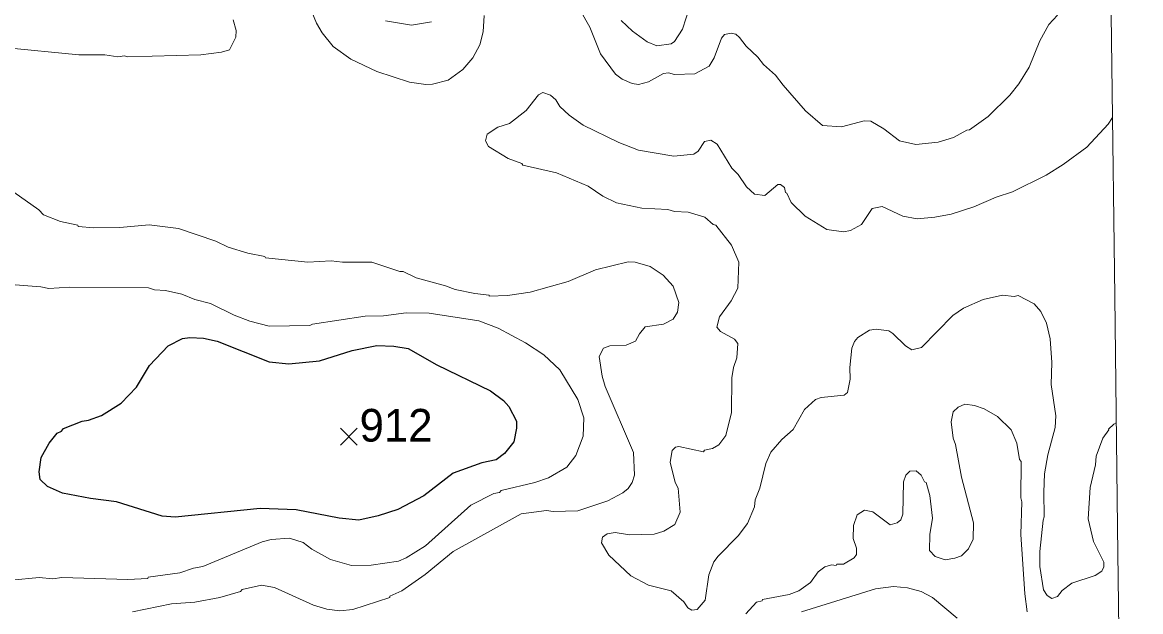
# Model space of a CAD drawing. Extents: x 265.7 to 292.1, y 7676.2 to 7704.2.
# Drawn here: x 289.24 to 291.975, y 7691.003 to 7692.446 of the extents above; entities that cross this region are included whole.
import ezdxf
from ezdxf.enums import TextEntityAlignment as Align

# ---------------------------------------------------------------- set-up
doc = ezdxf.new("R2010")
doc.units = 0
doc.header["$LTSCALE"] = 0.032
for name, color, linetype, lineweight in [('1', 7, 'Continuous', 25), ('2', 7, 'Continuous', 13), ('21', 7, 'Continuous', 25), ('63', 7, 'Continuous', 25)]:
    doc.layers.add(name, color=color, linetype=linetype, lineweight=lineweight)
doc.layers.add('61', color=7, linetype='Continuous')

msp = doc.modelspace()

# ---------------------------------------------------------------- linework, layer by layer
at = {"layer": '1'}
msp.add_lwpolyline([(289.9665, 7691.6176), (290.0463, 7691.6424), (290.107, 7691.6551), (290.1485, 7691.6535), (290.1836, 7691.648), (290.2538, 7691.6073), (290.3847, 7691.5442), (290.4166, 7691.5203), (290.4293, 7691.5059), (290.4485, 7691.47), (290.4485, 7691.4525), (290.4421, 7691.419), (290.419, 7691.3902), (290.399, 7691.375), (290.3639, 7691.3679), (290.2937, 7691.3423), (290.2219, 7691.2873), (290.158, 7691.2538), (290.1102, 7691.2378), (290.0623, 7691.2274), (290.0144, 7691.2322), (289.9091, 7691.253), (289.8213, 7691.2561), (289.6138, 7691.2346), (289.5819, 7691.237), (289.4702, 7691.2721), (289.4064, 7691.2801), (289.3377, 7691.2937), (289.301, 7691.3096), (289.2835, 7691.3272), (289.2803, 7691.3455), (289.2859, 7691.3806), (289.305, 7691.4158), (289.325, 7691.4405), (289.3353, 7691.4453), (289.3401, 7691.4517), (289.3856, 7691.47), (289.4016, 7691.4724), (289.4335, 7691.4836), (289.4814, 7691.5139), (289.5189, 7691.553), (289.5508, 7691.6057), (289.5963, 7691.6543), (289.6314, 7691.6719), (289.6489, 7691.6743), (289.6825, 7691.6727), (289.716, 7691.6655), (289.8436, 7691.6152), (289.8915, 7691.6104)], close=True, dxfattribs=at)
at = {"layer": '2'}
for points in [[(289.9362, 7692.4994), (289.9593, 7692.4435), (289.9729, 7692.4204), (290, 7692.3869), (290.0431, 7692.3557), (290.107, 7692.3254), (290.1868, 7692.2991), (290.2267, 7692.2935), (290.2426, 7692.2943), (290.2809, 7692.3047), (290.3168, 7692.3302), (290.3416, 7692.3589), (290.3583, 7692.3909), (290.3671, 7692.4228), (290.3695, 7692.4627)], [(290.8722, 7692.485), (290.8547, 7692.4292), (290.8347, 7692.3988), (290.8267, 7692.3933), (290.7916, 7692.3885), (290.7677, 7692.398), (290.7318, 7692.4244), (290.7046, 7692.4507)], [(290.6041, 7692.4755), (290.628, 7692.434), (290.6536, 7692.3685), (290.6903, 7692.3191), (290.707, 7692.3071), (290.731, 7692.2959), (290.7469, 7692.2935), (290.7709, 7692.3007), (290.8076, 7692.3206), (290.8204, 7692.3222), (290.8347, 7692.3182), (290.885, 7692.3198), (290.9201, 7692.339), (290.9321, 7692.3589), (290.9496, 7692.4068), (290.9576, 7692.4164), (290.9736, 7692.4196), (290.9847, 7692.4172), (290.9943, 7692.4092), (291.0103, 7692.3877), (291.039, 7692.3605), (291.0525, 7692.343), (291.0821, 7692.3167), (291.1004, 7692.2919), (291.1555, 7692.2297), (291.197, 7692.1938), (291.2433, 7692.1898), (291.2991, 7692.2049), (291.3151, 7692.2041), (291.347, 7692.185), (291.3853, 7692.1563), (291.4252, 7692.1467), (291.4795, 7692.1523), (291.5178, 7692.1642), (291.5497, 7692.1818), (291.5569, 7692.1826), (291.6024, 7692.2153), (291.655, 7692.268), (291.6774, 7692.2951), (291.7029, 7692.3366), (291.7284, 7692.4004), (291.7508, 7692.4403), (291.7715, 7692.4635)], [(288.8063, 7692.4491), (288.8781, 7692.4379), (288.8941, 7692.4379), (288.9659, 7692.4236), (288.9818, 7692.4236), (289.0074, 7692.4164), (289.1766, 7692.3901), (289.1941, 7692.3845), (289.3776, 7692.3661), (289.4415, 7692.3661), (289.4734, 7692.3613), (289.4894, 7692.3637), (289.4973, 7692.3613), (289.6761, 7692.3661), (289.7271, 7692.3733), (289.7463, 7692.3789), (289.7615, 7692.41), (289.763, 7692.426), (289.7551, 7692.4523)], [(290.2402, 7692.4475), (290.1916, 7692.4387), (290.1277, 7692.4499)], [(290.9751, 7691.5754), (290.9791, 7691.6009), (290.9871, 7691.6248), (290.9895, 7691.6599), (290.9815, 7691.6703), (290.9472, 7691.6895), (290.9384, 7691.6998), (290.9448, 7691.7254), (290.9736, 7691.7645), (290.9895, 7691.7956), (290.9919, 7691.8586), (290.9744, 7691.9009), (290.936, 7691.9496), (290.9297, 7691.9512), (290.9089, 7691.9687), (290.8682, 7691.9815), (290.8347, 7691.9831), (290.8188, 7691.9879), (290.7549, 7691.9911), (290.6927, 7692.0038), (290.6592, 7692.0206), (290.6241, 7692.0453), (290.5459, 7692.0773), (290.4637, 7692.0964), (290.4613, 7692.1004), (290.4278, 7692.1124), (290.3799, 7692.1419), (290.3727, 7692.1563), (290.3767, 7692.1722), (290.403, 7692.189), (290.4309, 7692.1986), (290.4724, 7692.2305), (290.502, 7692.2688), (290.5131, 7692.2744), (290.5315, 7692.268), (290.545, 7692.256), (290.5546, 7692.2401), (290.577, 7692.2185), (290.6113, 7692.1946), (290.6991, 7692.1515), (290.7469, 7692.1331), (290.8331, 7692.118), (290.8826, 7692.1235), (290.893, 7692.1307), (290.9081, 7692.1539), (290.9241, 7692.1579), (290.9392, 7692.1475), (290.9751, 7692.0892), (290.9903, 7692.0733), (291.0111, 7692.043), (291.0302, 7692.0254), (291.0557, 7692.0222), (291.0877, 7692.0493), (291.0941, 7692.0493), (291.1036, 7692.0414), (291.1068, 7692.0294), (291.11, 7692.0278), (291.1204, 7692.0047), (291.1547, 7691.9711), (291.2074, 7691.9392), (291.2481, 7691.9328), (291.2656, 7691.9368), (291.2927, 7691.9512), (291.3183, 7691.9903), (291.343, 7691.9951), (291.3933, 7691.9711), (291.4284, 7691.9647), (291.4715, 7691.9687), (291.5114, 7691.9767), (291.5672, 7691.9943), (291.6215, 7692.0182), (291.6614, 7692.031), (291.7444, 7692.0717), (291.7859, 7692.098), (291.8433, 7692.1403), (291.896, 7692.197), (291.9065, 7692.2129)], [(289.55, 7691.9504), (289.4782, 7691.944), (289.4143, 7691.9432), (289.376, 7691.9464), (289.3752, 7691.9496), (289.333, 7691.9584), (289.2915, 7691.9751), (289.2795, 7691.9871), (289.1095, 7692.1068)], [(289.8341, 7691.8698), (289.8325, 7691.873), (289.791, 7691.881), (289.7431, 7691.8953), (289.7128, 7691.9105), (289.6218, 7691.9416), (289.55, 7691.9504)], [(289.5093, 7691.0032), (289.6043, 7691.0224), (289.6617, 7691.0271), (289.7224, 7691.0383), (289.7734, 7691.0527), (289.7774, 7691.0575), (289.8245, 7691.0686), (289.8564, 7691.0623), (289.9522, 7691.0192), (289.9841, 7691.0096), (290.016, 7691.0056), (290.0479, 7691.0088), (290.1389, 7691.0383), (290.1389, 7691.0415), (290.1676, 7691.0543), (290.2251, 7691.0942), (290.2937, 7691.1508), (290.4597, 7691.2426), (290.5219, 7691.2514), (290.5379, 7691.249), (290.5985, 7691.2506), (290.6719, 7691.2745), (290.7086, 7691.2945), (290.7214, 7691.3048), (290.731, 7691.3192), (290.7374, 7691.3376), (290.735, 7691.3934), (290.6655, 7691.5546), (290.6576, 7691.5801), (290.6504, 7691.628), (290.6616, 7691.6488), (290.6767, 7691.6543), (290.7166, 7691.6559), (290.7398, 7691.6655), (290.7493, 7691.6839), (290.7629, 7691.7006), (290.8076, 7691.707), (290.8315, 7691.7198), (290.8419, 7691.7365), (290.8459, 7691.7605), (290.8315, 7691.8004), (290.8068, 7691.8275), (290.7757, 7691.8482), (290.739, 7691.8586), (290.7214, 7691.8594), (290.6416, 7691.8403), (290.5746, 7691.8115), (290.482, 7691.7852), (290.4262, 7691.7772), (290.3815, 7691.7756), (290.3815, 7691.778), (290.3464, 7691.782), (290.2985, 7691.7924), (290.2745, 7691.8012), (290.2027, 7691.8203), (290.1708, 7691.8363), (290.1628, 7691.8363), (290.0942, 7691.8586), (290.0224, 7691.8586), (289.9953, 7691.8618), (289.9378, 7691.8586), (289.8341, 7691.8698)], [(289.2117, 7691.8044), (289.2851, 7691.7988), (289.3042, 7691.7948), (289.3553, 7691.798), (289.5484, 7691.7964), (289.5628, 7691.7916), (289.5899, 7691.7892), (289.6298, 7691.7804), (289.6617, 7691.7677), (289.7, 7691.7581), (289.7575, 7691.7294), (289.7958, 7691.7142), (289.8436, 7691.7022), (289.9426, 7691.7038), (289.949, 7691.707), (290.0782, 7691.727), (290.1229, 7691.7278), (290.1788, 7691.7349), (290.2346, 7691.7341), (290.3559, 7691.715), (290.4038, 7691.6974), (290.4708, 7691.6615), (290.5155, 7691.632), (290.5546, 7691.5953), (290.5985, 7691.5227), (290.6129, 7691.478), (290.6113, 7691.4333), (290.5937, 7691.3854), (290.5714, 7691.3575), (290.5267, 7691.3312), (290.4932, 7691.3192), (290.411, 7691.3), (290.407, 7691.2953), (290.3926, 7691.2929), (290.3368, 7691.2641), (290.2259, 7691.1644), (290.1788, 7691.1349), (290.1596, 7691.1269), (290.0926, 7691.1173), (290.0447, 7691.1165), (289.9937, 7691.1309), (289.9474, 7691.1564), (289.9266, 7691.1724), (289.8931, 7691.1835), (289.8484, 7691.1804), (289.8261, 7691.174), (289.6809, 7691.1141), (289.6585, 7691.1101), (289.625, 7691.0982), (289.5476, 7691.0878), (289.5468, 7691.0846), (289.4973, 7691.0822), (289.3361, 7691.087), (289.3138, 7691.0838), (289.2803, 7691.087), (289.2133, 7691.0806)], [(291.9157, 7691.4659), (291.9097, 7691.4627), (291.8963, 7691.4505), (291.8976, 7691.4485), (291.8824, 7691.4285), (291.8665, 7691.3838), (291.8649, 7691.3631), (291.8521, 7691.3072), (291.8465, 7691.2306), (291.8601, 7691.1748), (291.8848, 7691.1245), (291.8848, 7691.1133), (291.88, 7691.1022), (291.8641, 7691.0918), (291.8066, 7691.0734), (291.7835, 7691.0551), (291.7715, 7691.0407), (291.758, 7691.0359), (291.7468, 7691.0431), (291.7372, 7691.0567), (291.7284, 7691.1141), (291.7284, 7691.1508), (291.7364, 7691.2274), (291.7396, 7691.2354), (291.738, 7691.2961), (291.7404, 7691.3407), (291.7484, 7691.387), (291.7659, 7691.4541), (291.7675, 7691.4828), (291.7564, 7691.5594), (291.758, 7691.6137), (291.754, 7691.6711), (291.7452, 7691.7094), (291.7308, 7691.7381), (291.7149, 7691.7573), (291.6758, 7691.7772), (291.6662, 7691.7748), (291.6375, 7691.778), (291.5896, 7691.7677), (291.5417, 7691.7461), (291.5154, 7691.7286), (291.4388, 7691.6504), (291.4156, 7691.644), (291.3997, 7691.6543), (291.3693, 7691.6847), (291.359, 7691.691), (291.3279, 7691.695), (291.3119, 7691.6926), (291.2832, 7691.6743), (291.2752, 7691.6647), (291.2688, 7691.6488), (291.264, 7691.6009), (291.2648, 7691.5722), (291.2584, 7691.5402), (291.2497, 7691.5331), (291.1938, 7691.5275), (291.1802, 7691.5227), (291.1531, 7691.4979), (291.1252, 7691.4493), (291.0972, 7691.4245), (291.0709, 7691.3942), (291.0581, 7691.3663), (291.0438, 7691.3056), (291.0326, 7691.2769), (291.031, 7691.2602), (291.0135, 7691.2195), (290.9903, 7691.1891), (290.9416, 7691.1397), (290.9313, 7691.1253), (290.9193, 7691.0934), (290.9097, 7691.0319), (290.8906, 7691.0088), (290.877, 7691.0072), (290.8674, 7691.0128), (290.8579, 7691.0279), (290.8267, 7691.0543), (290.7709, 7691.0686), (290.7278, 7691.091), (290.6743, 7691.1421), (290.656, 7691.1716), (290.6584, 7691.1859), (290.6703, 7691.1939), (290.6895, 7691.1971), (290.7246, 7691.1915), (290.7852, 7691.1931), (290.8092, 7691.2003), (290.8355, 7691.2171), (290.8491, 7691.2466), (290.8435, 7691.3056), (290.8363, 7691.32), (290.8243, 7691.3695), (290.8291, 7691.3982), (290.8371, 7691.4062), (290.8459, 7691.4078), (290.9057, 7691.395)], [(290.9057, 7691.395), (290.9081, 7691.399), (290.9281, 7691.403), (290.9432, 7691.4118), (290.9608, 7691.4349), (290.9744, 7691.4908), (290.9751, 7691.5754)], [(291.6973, 7691.0032), (291.6917, 7691.0471), (291.6821, 7691.1923), (291.6845, 7691.2721), (291.6821, 7691.2817), (291.6829, 7691.3711), (291.679, 7691.3759), (291.6726, 7691.4158), (291.6582, 7691.4485), (291.6247, 7691.4812), (291.5928, 7691.5003), (291.5688, 7691.5083), (291.5449, 7691.5115), (291.5289, 7691.5043), (291.5162, 7691.4924), (291.5114, 7691.4684), (291.5162, 7691.4285), (291.5226, 7691.4126), (291.5369, 7691.3328), (291.5664, 7691.2211), (291.5656, 7691.1812), (291.5545, 7691.1572), (291.5369, 7691.1405), (291.521, 7691.1341), (291.497, 7691.1301), (291.4723, 7691.1381), (291.4587, 7691.1532), (291.4595, 7691.1923), (291.4659, 7691.2322), (291.4595, 7691.2881), (291.4507, 7691.32), (291.4467, 7691.3216), (291.438, 7691.3376), (291.426, 7691.3479), (291.4108, 7691.3471), (291.4005, 7691.3375), (291.3949, 7691.3216), (291.3933, 7691.2418), (291.3885, 7691.2282), (291.3797, 7691.2211), (291.3622, 7691.2163), (291.3199, 7691.2482), (291.2999, 7691.2522), (291.2816, 7691.2402), (291.2728, 7691.2147), (291.272, 7691.1828), (291.28, 7691.1588), (291.28, 7691.1437), (291.2744, 7691.1349), (291.2481, 7691.1197), (291.2321, 7691.1197), (291.2305, 7691.1165), (291.2193, 7691.1181), (291.2026, 7691.1133), (291.1866, 7691.1006), (291.1675, 7691.075), (291.1387, 7691.0543), (291.1156, 7691.0455), (291.0502, 7691.0335), (291.0494, 7691.0303), (291.0358, 7691.0263), (291.0095, 7690.9984)], [(291.1459, 7691.0032), (291.3263, 7691.0591), (291.3709, 7691.0654), (291.4045, 7691.0615), (291.438, 7691.0527), (291.4659, 7691.0383), (291.5265, 7690.9872)]]:
    msp.add_lwpolyline(points, dxfattribs=at)
at = {"layer": '21'}
for p, q in [((290.0178, 7691.4522), (290.059, 7691.411)), ((290.059, 7691.4522), (290.0178, 7691.411))]:
    msp.add_line(p, q, dxfattribs=at)
at = {"layer": '63', "lineweight": 13}
msp.add_lwpolyline([(291.8978, 7692.9047), (291.9049, 7692.3398), (291.9119, 7691.7749), (291.9189, 7691.21), (291.9259, 7690.6451), (291.933, 7690.0801), (291.94, 7689.5152), (291.947, 7688.9503), (291.9541, 7688.3854), (291.9611, 7687.8205), (291.9681, 7687.2556), (291.9752, 7686.6906)], dxfattribs=at)

# ---------------------------------------------------------------- texts
at = {"layer": '61'}
msp.add_text('912', height=0.08, dxfattribs=at).set_placement((290.1538, 7691.4197), align=Align.CENTER)

doc.saveas('drawing.dxf')
